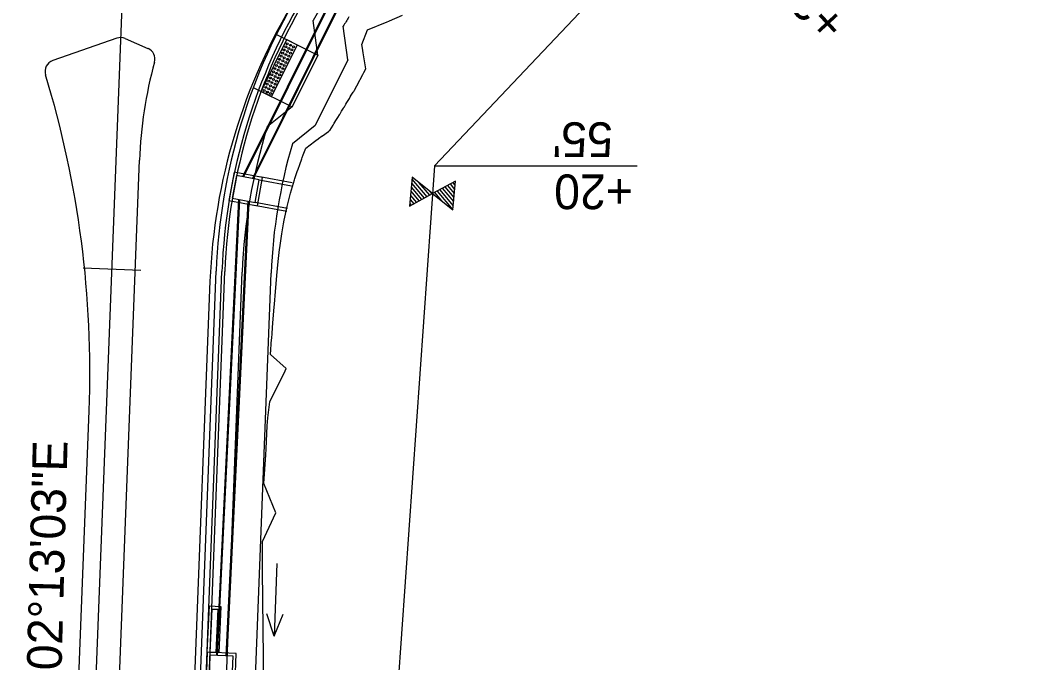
# Model space of a CAD drawing. Extents: x 670017 to 673226, y 705371 to 707498.
# Drawn here: x 671704.7 to 671881.1, y 706314 to 706424.9 of the extents above; entities that cross this region are included whole.
import ezdxf

# ---------------------------------------------------------------- set-up
doc = ezdxf.new("R2010")
doc.units = 0
for name, color, linetype in [('EL R SCBV', 7, 'Continuous'), ('R_Drainage Flow Lines', 7, 'Continuous'), ('R_Drainage Stage 1A', 7, 'Continuous'), ('R_Drainage Stage 2', 7, 'Continuous'), ('R_Fence', 7, 'Continuous'), ('R_Horz Alg', 7, 'Continuous'), ('R_Horz Alg Station', 7, 'Continuous'), ('R_Horz Bearing', 7, 'Continuous'), ('R_No Plot FOC', 7, 'Continuous'), ('R_Proposed Const Limits Stage 2', 7, 'Continuous'), ('R_Proposed Median', 7, 'Continuous'), ('R_Proposed Road Stage 2', 7, 'Continuous'), ('R_Proposed Sidewalk Stage 2', 7, 'Continuous'), ('R_ROW', 7, 'Continuous'), ('R_ROW Annot', 7, 'Continuous'), ('R_Water Annot', 7, 'Continuous')]:
    doc.layers.add(name, color=color, linetype=linetype)

# ---------------------------------------------------------------- blocks, each defined once
blk = doc.blocks.new('FLOW ARROW')
at = {"layer": 'R_Water Annot'}
for p, q in [((-12.57, 0), (0, 0)), ((0, 0), (-3.85, 1.4)), ((0, 0), (-3.85, -1.4))]:
    blk.add_line(p, q, dxfattribs=at)

msp = doc.modelspace()

# ---------------------------------------------------------------- linework, layer by layer
at = {"layer": 'EL R SCBV'}
msp.add_line((671737.48, 706379.84), (671729.41, 706171.45), dxfattribs=at)
msp.add_arc((671838.41, 706375.93), 101, 148.4842, 177.7825, dxfattribs=at)
at = {"layer": 'R_Drainage Stage 1A'}
for points in [[(671737, 706315.76), (671737.38, 706323.75), (671739.38, 706323.66), (671739, 706315.67)], [(671737.5, 706315.74), (671737.86, 706323.23), (671738.86, 706323.18), (671738.5, 706315.69)]]:
    msp.add_lwpolyline(points, close=True, dxfattribs=at)
at = {"layer": 'R_Drainage Stage 2'}
for p, q in [((671769.73, 706451.43), (671743.1, 706397.91)), ((671769.86, 706451.33), (671743.27, 706397.88)), ((671771.1, 706450.45), (671744.8, 706397.59)), ((671771.24, 706450.35), (671744.97, 706397.56)), ((671751.68, 706396.82), (671746.09, 706397.86)), ((671746, 706397.37), (671751.59, 706396.33)), ((671742.39, 706393.97), (671738.59, 706315.2)), ((671742.56, 706393.94), (671738.75, 706315.19)), ((671744.05, 706393.66), (671740.25, 706315.13)), ((671744.21, 706393.63), (671740.42, 706315.13)), ((671750.77, 706391.9), (671745.18, 706392.94)), ((671750.86, 706392.4), (671745.27, 706393.44))]:
    msp.add_line(p, q, dxfattribs=at)
for points in [[(671745.67, 706392.85), (671746.58, 706397.77), (671741.67, 706398.68), (671740.75, 706393.77)], [(671745.27, 706393.44), (671746, 706397.37), (671742.07, 706398.1), (671741.34, 706394.17)], [(671741.81, 706310.57), (671742, 706315.57), (671737, 706315.76), (671736.81, 706310.76)], [(671741.33, 706311.09), (671741.48, 706315.09), (671737.48, 706315.24), (671737.33, 706311.24)]]:
    msp.add_lwpolyline(points, close=True, dxfattribs=at)
at = {"layer": 'R_Fence'}
for p, q in [((671772.25, 706396.09), (671774.03, 706393.96)), ((671772.31, 706396.79), (671774.48, 706394.21)), ((671772.37, 706397.5), (671774.93, 706394.45)), ((671773.5, 706396.93), (671775.38, 706394.7)), ((671777.61, 706395.92), (671779.56, 706393.6)), ((671778.06, 706396.17), (671779.62, 706394.31)), ((671778.51, 706396.41), (671779.68, 706395.01)), ((671778.95, 706396.66), (671779.75, 706395.72)), ((671779.4, 706396.9), (671779.81, 706396.42)), ((671779.85, 706397.15), (671779.87, 706397.12)), ((671772.13, 706394.68), (671773.14, 706393.47)), ((671772.19, 706395.38), (671773.59, 706393.72)), ((671775.49, 706395.34), (671775.82, 706394.94)), ((671776.27, 706395.19), (671777.48, 706393.75)), ((671776.72, 706395.43), (671779.44, 706392.19)), ((671777.16, 706395.68), (671779.5, 706392.9)), ((671772, 706393.27), (671772.25, 706392.98)), ((671772.07, 706393.97), (671772.69, 706393.23))]:
    msp.add_line(p, q, dxfattribs=at)
msp.add_lwpolyline([(671775.93, 706395), (671775.91, 706395), (671772.4, 706397.81), (671771.97, 706392.83), (671775.91, 706394.99), (671775.93, 706394.99), (671779.44, 706392.18), (671779.87, 706397.16), (671775.93, 706395)], dxfattribs=at)
at = {"layer": 'R_Horz Alg'}
msp.add_line((671681.86, 705382.69), (671726.73, 706541.35), dxfattribs=at)
at = {"layer": 'R_Horz Alg Station'}
msp.add_lwpolyline([(671715.56, 706382.14), (671725.55, 706381.75)], dxfattribs=at)
msp.add_lwpolyline([(671715.56, 706382.14), (671725.55, 706381.75)], dxfattribs=at)
at = {"layer": 'R_No Plot FOC'}
msp.add_line((671731.41, 706171.36), (671739.55, 706381.55), dxfattribs=at)
msp.add_arc((671839.48, 706377.68), 100, 148.4842, 177.7825, dxfattribs=at)
at = {"layer": 'R_Proposed Const Limits Stage 2'}
for points in [[(671764.67, 706423.26), (671768.1, 706424.66), (671768.37, 706424.78), (671768.51, 706424.84), (671770.76, 706425.83)], [(671754.04, 706402.86), (671755.52, 706403.97), (671755.75, 706404.14), (671756.17, 706404.44), (671756.24, 706404.49), (671756.87, 706404.94), (671756.94, 706404.99), (671757.94, 706405.71), (671758.1, 706405.82), (671758.19, 706405.88), (671758.75, 706406.8), (671758.88, 706407.01), (671758.91, 706407.07), (671758.95, 706407.13), (671758.96, 706407.15), (671759.35, 706407.79), (671759.56, 706408.13), (671759.83, 706408.57), (671759.86, 706408.63), (671759.95, 706408.77), (671760.23, 706409.23), (671760.55, 706409.75), (671760.68, 706409.97), (671760.7, 706410), (671760.9, 706410.33), (671760.95, 706410.41), (671761.14, 706410.72), (671761.56, 706411.41), (671761.57, 706411.43), (671761.72, 706411.68), (671761.9, 706411.98), (671762.22, 706412.49), (671762.31, 706412.64), (671762.43, 706412.85), (671762.45, 706412.88), (671762.84, 706413.58), (671762.86, 706413.61), (671763.38, 706414.59), (671763.43, 706414.67), (671763.91, 706415.56), (671764.09, 706415.91), (671764.38, 706416.56), (671764.17, 706417.93), (671763.95, 706419.33), (671763.82, 706420.13), (671763.73, 706420.76), (671764.67, 706423.26)], [(671747.91, 706367.21), (671748.13, 706369.87), (671748.14, 706369.93), (671748.21, 706370.87), (671748.36, 706372.65), (671748.58, 706375.36), (671748.62, 706375.86), (671748.8, 706378.07), (671749.02, 706380.77), (671749.03, 706380.84), (671749.26, 706383.23), (671749.51, 706385.33), (671749.55, 706385.63), (671749.88, 706388.02), (671750.16, 706389.77), (671750.27, 706390.39), (671750.81, 706392.74), (671751.18, 706394.15), (671751.42, 706395.06), (671752.09, 706397.36), (671752.16, 706397.59), (671752.39, 706398.3), (671752.57, 706398.82), (671752.71, 706399.22), (671753, 706400.04), (671753.34, 706400.99), (671753.43, 706401.25), (671753.59, 706401.67), (671754.04, 706402.86)], [(671747.46, 706356.28), (671747.82, 706359.01), (671748.24, 706359.86), (671749.12, 706361.64), (671749.14, 706361.69), (671750.46, 706364.37), (671750.66, 706364.77), (671747.91, 706367.21)], [(671746.81, 706344.9), (671747.11, 706349.89), (671747.17, 706350.89), (671747.39, 706354.89), (671747.46, 706356.28)], [(671746.53, 706334.91), (671748.88, 706339.82), (671746.81, 706344.9)], [(671746.74, 706309.88), (671746.7, 706314.88), (671746.66, 706319.89), (671746.62, 706324.89), (671746.58, 706329.9), (671746.53, 706334.91)]]:
    msp.add_lwpolyline(points, dxfattribs=at)
at = {"layer": 'R_Proposed Median'}
for p, q in [((671721.38, 706421.82), (671710.32, 706417.95)), ((671722.84, 706421.77), (671726.77, 706420.06)), ((671717.19, 706191.78), (671725.28, 706400.74)), ((671709.43, 706172.22), (671716.6, 706357.48))]:
    msp.add_line(p, q, dxfattribs=at)
for centre, radius, start, end in [((671722.04, 706419.93), 2, 66.5337, 109.2743), ((671725.98, 706418.23), 2, 344.6466, 66.5337), ((671710.98, 706416.07), 2, 109.2743, 197.023), ((671800.23, 706397.84), 75, 164.6466, 177.7825), ((671541.73, 706364.25), 175, 357.7825, 17.023)]:
    msp.add_arc(centre, radius, start, end, dxfattribs=at)
at = {"layer": 'R_Proposed Road Stage 2'}
for p, q in [((671730.41, 706171.41), (671738.55, 706381.58)), ((671731.91, 706171.35), (671740.05, 706381.53))]:
    msp.add_line(p, q, dxfattribs=at)
for radius in [101, 99.5]:
    msp.add_arc((671839.48, 706377.68), radius, 148.4842, 177.7825, dxfattribs=at)
at = {"layer": 'R_Proposed Sidewalk Stage 2'}
for p, q in [((671756.12, 706418.92), (671755.32, 706424.9)), ((671748.95, 706422.47), (671756.12, 706418.92)), ((671761.28, 706418.07), (671760.5, 706423.88)), ((671752.54, 706420.7), (671748.11, 706411.73)), ((671756.12, 706418.92), (671751.69, 706409.96)), ((671761.28, 706418.07), (671755.68, 706406.75)), ((671744.96, 706413.29), (671751.69, 706409.96)), ((671751.69, 706409.96), (671747.39, 706406.51)), ((671755.68, 706406.75), (671751.72, 706403.58)), ((671734.91, 706171.23), (671743.05, 706381.41)), ((671739.91, 706171.04), (671748.05, 706381.22))]:
    msp.add_line(p, q, dxfattribs=at)
msp.add_lwpolyline([(671746.31, 706412.62), (671750.75, 706421.58), (671752.54, 706420.7), (671748.11, 706411.73)], close=True, dxfattribs=at)
for centre in [(671750.84, 706420.87), (671751.38, 706420.6), (671749.78, 706418.72), (671750.04, 706419.25), (671750.31, 706419.79), (671750.58, 706420.33), (671750.58, 706418.99), (671750.85, 706419.53), (671751.11, 706420.06), (671751.12, 706418.72), (671751.39, 706419.26), (671751.65, 706419.8), (671751.92, 706420.34), (671748.98, 706417.1), (671749.25, 706417.64), (671749.51, 706418.18), (671749.78, 706417.37), (671750.05, 706417.91), (671750.32, 706418.45), (671750.32, 706417.11), (671750.59, 706417.65), (671750.85, 706418.18), (671748.18, 706415.49), (671748.45, 706416.03), (671748.71, 706416.57), (671748.72, 706415.22), (671748.99, 706415.76), (671749.25, 706416.3), (671749.52, 706416.84), (671749.52, 706415.5), (671749.79, 706416.03), (671750.06, 706416.57), (671747.12, 706413.34), (671747.38, 706413.88), (671747.65, 706414.41), (671747.92, 706414.95), (671747.92, 706413.61), (671748.19, 706414.15), (671748.45, 706414.69), (671748.46, 706413.34), (671748.72, 706413.88), (671748.99, 706414.42), (671749.26, 706414.96), (671746.85, 706412.8), (671747.39, 706412.53), (671747.65, 706413.07), (671747.93, 706412.27), (671748.19, 706412.81)]:
    msp.add_circle(centre, 0.165, dxfattribs=at)
for radius, start, end in [(96.5, 148.4842, 150.7012), (91.5, 148.4842, 149.6675), (96.5, 162.6136, 177.7825), (91.5, 163.5563, 177.7825)]:
    msp.add_arc((671839.48, 706377.68), radius, start, end, dxfattribs=at)
at = {"layer": 'R_ROW'}
msp.add_lwpolyline([(672596.28, 706451.05), (672596.28, 706451.05), (672161.7, 706463.84), (671891.46, 706473.02), (671825.24, 706451.46), (671776.29, 706399.8), (671754.1, 706085.43), (671832.11, 706032.37), (671817.47, 705912.84), (671726.19, 705881.35)], dxfattribs=at)
at = {"layer": 'R_ROW Annot'}
msp.add_lwpolyline([(671776.29, 706399.8), (671791.29, 706399.8), (671811.29, 706399.8)], dxfattribs=at)

# ---------------------------------------------------------------- block references
at = {"layer": 'R_Drainage Flow Lines', "rotation": -92.21751391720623}
msp.add_blockref('FLOW ARROW', (671748.57, 706318.52), dxfattribs=at)

# ---------------------------------------------------------------- texts
at = {"layer": 'R_Horz Bearing'}
msp.add_text('N02%%d13\'03"E', height=6, rotation=88.4794, dxfattribs=at).set_placement((671711.68, 706306.78))
at = {"layer": 'R_ROW Annot'}
for s, rotation, p in [('+30', 132.7034, (671847.9, 706424.69)), ("55'", 180, (671807.09, 706407.3)), ('+20', 180, (671810.55, 706398.3))]:
    msp.add_text(s, height=6, rotation=rotation, dxfattribs=at).set_placement(p)

doc.saveas('drawing.dxf')
